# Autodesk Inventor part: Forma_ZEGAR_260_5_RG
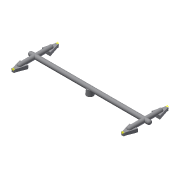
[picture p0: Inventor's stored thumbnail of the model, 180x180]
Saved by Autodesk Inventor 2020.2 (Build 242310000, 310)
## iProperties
Created: 2015-01
Part Number: Forma_ZEGAR_260_5_RG
Material: Ogólny
Document SubType Name: Modeling
Designer: F.Stasiak
Density: 1 g/cm^3
Appearance: Domyślna
Catalog Web Link: www.expertbooks.pl
Manager: www.cadconsulting.pl
Company: Fabian Stasiak CAD Consulting
Author: F.Stasiak
Subject: Zbiór ćwiczeń. Autodesk Inventor 2020. Kurs Professional
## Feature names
1. Wyciągnięcie proste7 [Extrusion]
2. Przeciągnięcie1
3. Obrót1 [Revolution]
4. Wyciągnięcie proste1 [Extrusion]
5. Przeciągnięcie2
6. Obrót2 [Revolution]
7. Wyciągnięcie proste2 [Extrusion]
8. Przeciągnięcie3
9. Obrót3 [Revolution]
10. Wyciągnięcie proste3 [Extrusion]
11. Przeciągnięcie4
12. Obrót4 [Revolution]
13. Wyciągnięcie proste4 [Extrusion]
14. Przeciągnięcie5
15. Obrót5 [Revolution]
16. Wyciągnięcie proste5 [Extrusion]
17. Przeciągnięcie6
18. Obrót6 [Revolution]
19. Wyciągnięcie proste6 [Extrusion]
20. Wyciągnięcie złożone1
21. Wyciągnięcie złożone2
22. Wyciągnięcie złożone3
23. Wyciągnięcie złożone4
## Parameters: d0 = -9.8085 mm, d1 = 39 mm, d2 = 8 mm, d3 = 3 mm, d4 = 0, d5 = 0, d6 = -3 mm, d7 = 3 mm, d8 = 180 deg, d9 = 3 mm, d10 = 3 mm, d11 = 0, d12 = 3 mm, d13 = 0, d14 = 0, d15 = -3 mm, d16 = 3 mm, d17 = 180 deg, d18 = 3 mm, d19 = 3 mm, d20 = 0, d21 = 3 mm, d22 = 0, d23 = 0, d24 = 3 mm, d25 = 3 mm, d26 = 180 deg, d27 = 3 mm, d28 = 3 mm, d29 = 0, d30 = 3 mm, d31 = 0, d32 = 0, d33 = 3 mm, d34 = 3 mm, d35 = 180 deg, d36 = 3 mm, d37 = 3 mm, d38 = 0, d39 = 3 mm, d40 = 0, d41 = 0, d42 = 3 mm, d43 = 3 mm, d44 = 180 deg, d45 = 3 mm, d46 = 3 mm, d47 = 0, d48 = 3 mm, d49 = 0, d50 = 0, d51 = 3 mm, d52 = 3 mm, d53 = 180 deg, d54 = 3 mm, d55 = 3 mm, d56 = 0, d58 = 2 mm, d59 = 2 mm, d60 = 87 deg, d61 = 87 deg, d62 = 6 mm, d63 = 2.5 mm, d64 = 87 deg, d65 = 87 deg, d66 = 0, d67 = 90 deg, d68 = 0, d69 = 90 deg, d70 = 1 mm, d72 = 2 mm, d73 = 2 mm, d74 = 87 deg, d75 = 87 deg, d76 = 6 mm, d77 = 2.5 mm, d78 = 87 deg, d79 = 87 deg, d80 = 0, d81 = 90 deg, d82 = 0, d83 = 90 deg, d84 = 1 mm, d86 = 2 mm, d87 = 2 mm, d88 = 87 deg, d89 = 87 deg, d90 = 6 mm, d91 = 2.5 mm, d92 = 87 deg, d93 = 87 deg, d94 = 0, d95 = 90 deg, d96 = 0, d97 = 90 deg, d98 = 1 mm, d100 = 2 mm, d101 = 2 mm, d102 = 87 deg, d103 = 87 deg, d104 = 6 mm, d105 = 2.5 mm, d106 = 87 deg, d107 = 87 deg, d108 = 0, d109 = 90 deg, d110 = 0, d111 = 90 deg, d112 = 1 mm, d113 = 4 mm, d114 = 5 deg, d115 = 1 mm, d116 = 1 mm, d117 = 1 mm, d118 = 1 mm
